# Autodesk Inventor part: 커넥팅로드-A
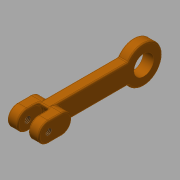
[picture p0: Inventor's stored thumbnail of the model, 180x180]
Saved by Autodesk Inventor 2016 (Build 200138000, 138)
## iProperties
Created: 2018-01
Part Number: 커넥팅로드-A
Material: 알루미늄 6061
Document SubType Name: Modeling
Designer: mduedu
Density: 2.71 g/cm^3
Appearance: 주황색
Mass: 5.11804 g
Surface Area: 16.3537 cm^2
Volume: 1.88857 cm^3
Author: mduedu
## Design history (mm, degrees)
sketch "스케치1"
  geometry: L1 (0, 0)-(0, 40); L2 (3.75, 40)-(3.75, 5.911); L3 (-3.75, 40)-(-3.75, 5.911); A1 r 7 centre (0, 0) between (3.75, 5.911) and (-3.75, 5.911); A2 r 3.75 centre (0, 40) between (3.75, 40) and (-3.75, 40); 1 further point
  constraints: 6 end point, 4 point on circle, 2 centre point, 2 coincident, 2 parallel, 2 tangent, 1 vertical
  dimensions: "d1" = 40 distance of L1.start L1.end; "d2" = 7.5 diameter of A2; "d3" = 14 diameter of A1
extrude "돌출1" new body sketch "스케치1" stored distance "d4" = 4; taper "d5" = 0 deg
sketch "스케치2"
  geometry: L1 (-3.75, 40)-(-3.75, 35); L2 (3.75, 40)-(3.75, 35); A1 r 3.75 centre (0, 40) between (3.75, 40) and (-3.75, 40) reference; A2 r 3.75 centre (0, 40) between (3.75, 40) and (-3.75, 40); A3 r 3.75 centre (0, 35) between (-3.75, 35) and (3.75, 35); 1 further point
  constraints: 4 end point, 4 point on circle, 2 centre point, 2 tangent, 1 coincident, 1 equal radius, 1 point on line, 1 vertical alignment
  dimensions: "d6" = 5 distance of A3.centre A1.centre
extrude "돌출2" join sketch "스케치2" stored distance "d7" = 12; taper "d8" = 0 deg
sketch "스케치3"
  geometry: L1 (3.75, 40)-(3.75, 38); L2 (-3.75, 40)-(-3.75, 38); A1 r 3.75 centre (0, 40) between (3.75, 40) and (-3.75, 40) reference; A2 r 3.75 centre (0, 40) between (3.75, 40) and (-3.75, 40); A3 r 3.75 centre (0, 38) between (-3.75, 38) and (3.75, 38); 1 further point
  constraints: 4 end point, 4 point on circle, 3 tangent, 2 centre point, 1 coincident, 1 equal radius, 1 parallel, 1 point on line
  dimensions: "d9" = 2 distance of A3.centre A1.centre
extrude "돌출3" cut sketch "스케치3" stored distance "d10" = 4; taper "d11" = 0 deg
fillet "모깎기5" dims "d16" = 0.5
fillet "모깎기6" dims "d17" = 0.5
fillet "모깎기7" dims "d18" = 0.5
fillet "모깎기8" dims "d19" = 0.5
hole "구멍1" diameter "d22" = 7.5; stored, may be unused: countersink angle "d26" = 90 deg, drill point angle "d28" = 118 deg; dims "d20" = 10, "d21" = 10, "d23" = 6, "d24" = 4, "d25" = 2, "d27" = 8
sketch "스케치4"
  geometry: A1 r 3.75 centre (40, 0) between (40, -3.75) and (40, 3.75) reference; 2 further points
  constraints: 1 coincident
sketch "스케치5"
  geometry: 1 further point
  constraints: 1 other
hole "구멍2" sketch "스케치5" at (40, 0) diameter "d29" = 2.459; stored, may be unused: countersink angle "d33" = 90 deg, drill point angle "d35" = 0 deg; dims "d30" = 6, "d31" = 4, "d32" = 2, "d34" = 8
sketch "스케치6"
  geometry: 1 further point
  constraints: 1 other
hole "구멍4" sketch "스케치6" at (-40, 0) diameter "d36" = 2.459; stored, may be unused: countersink angle "d40" = 90 deg, drill point angle "d42" = 0 deg; dims "d37" = 6, "d38" = 4, "d39" = 2, "d41" = 8
node "솔리드1"
